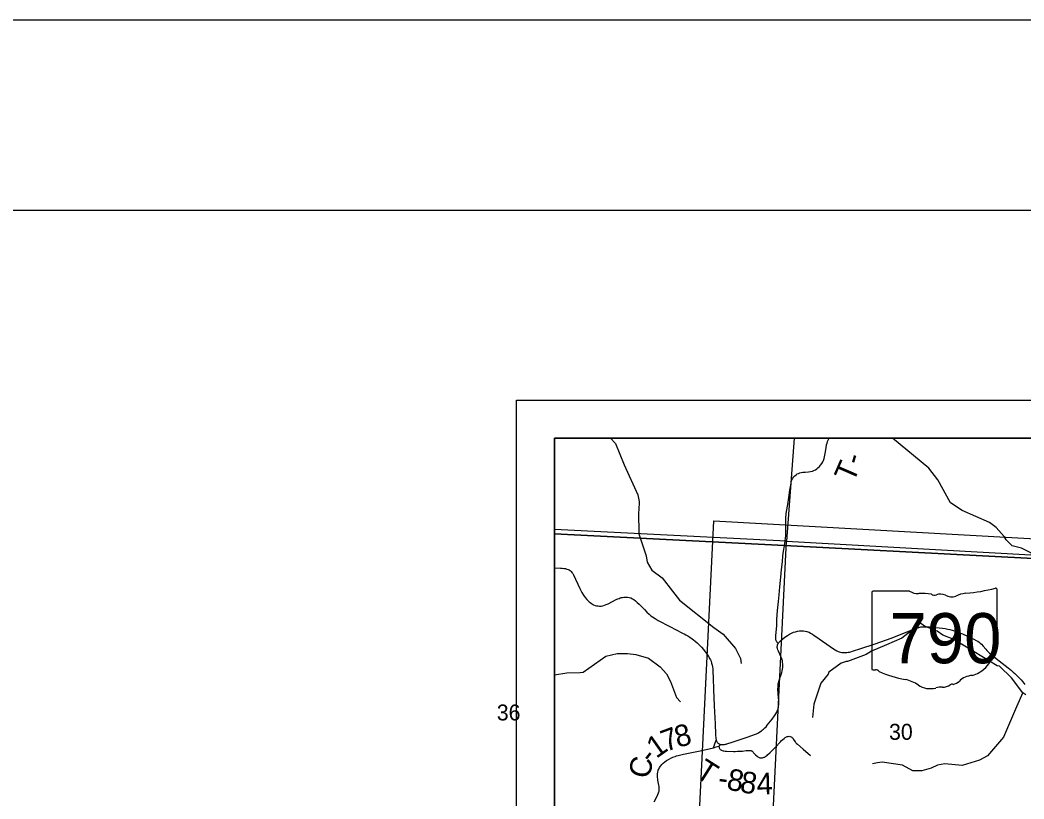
# Model space of a CAD drawing. Extents: x 0 to 34, y 0 to 22.
# Drawn here: x 22.432 to 25.071, y 19.951 to 22 of the extents above; entities that cross this region are included whole.
import ezdxf

# ---------------------------------------------------------------- set-up
doc = ezdxf.new("R2010")
doc.units = 0
for name, color, linetype in [('GM_X_County_Road', 7, 'Continuous'), ('GM_X_County_Road_Text', 7, 'Continuous'), ('GM_X_County_Text', 7, 'Continuous'), ('GM_X_Minor_River', 7, 'Continuous'), ('GM_X_Section', 7, 'Continuous'), ('GM_X_Section_Text', 7, 'Continuous'), ('GM_X_State_Location', 7, 'Continuous'), ('GM_X_State_Route', 7, 'Continuous'), ('GM_X_State_Shield', 7, 'Continuous'), ('GM_X_Township_Road', 7, 'Continuous'), ('GM_X_Township_Road_Text', 7, 'Continuous'), ('SH_Border', 7, 'Continuous'), ('SH_Cut_Line', 7, 'Continuous'), ('SH_Data', 7, 'Continuous')]:
    doc.layers.add(name, color=color, linetype=linetype)

msp = doc.modelspace()

# ---------------------------------------------------------------- linework, layer by layer
at = {"layer": 'GM_X_County_Road'}
for points in [[(24.0993, 19.9439), (24.1068, 19.9581), (24.1088, 19.9625), (24.1106, 19.9668), (24.1114, 19.9694), (24.112, 19.9719), (24.1124, 19.9747), (24.1125, 19.9775), (24.1126, 19.9805), (24.1124, 19.9839), (24.1119, 19.9873), (24.111, 19.9919), (24.1093, 20.0001), (24.1086, 20.0042), (24.1081, 20.0077), (24.1079, 20.012), (24.1082, 20.0171), (24.1089, 20.0214), (24.1101, 20.0264), (24.1112, 20.0293), (24.1135, 20.0339), (24.1164, 20.0381), (24.1192, 20.0414), (24.1228, 20.045), (24.1272, 20.0486), (24.1318, 20.0519), (24.1371, 20.0552), (24.1427, 20.0581), (24.1484, 20.0607), (24.1542, 20.0628), (24.1582, 20.0641), (24.1626, 20.0653), (24.1695, 20.0671), (24.1764, 20.0687), (24.2158, 20.0766), (24.2362, 20.0813), (24.2549, 20.0859), (24.2581, 20.0868), (24.2626, 20.0881), (24.2659, 20.089), (24.2692, 20.0902), (24.2703, 20.0907), (24.2711, 20.0912), (24.2718, 20.0918), (24.2722, 20.0925), (24.2727, 20.0936), (24.2731, 20.0946)], [(24.2549, 20.0859), (24.2569, 20.0908), (24.26, 20.0985), (24.2627, 20.1053)]]:
    msp.add_lwpolyline(points, dxfattribs=at)
at = {"layer": 'GM_X_County_Text'}
msp.add_lwpolyline([(28.6466, 20.9), (23.8372, 20.9), (23.8372, 20.6485), (24.4417, 20.6174), (26.0533, 20.5337), (26.781, 20.4973), (27.0539, 20.4845), (27.8401, 20.4449), (28.6062, 20.4055)], close=True, dxfattribs=at)
msp.add_lwpolyline([(28.4159, 17.3358), (28.4427, 17.7695), (28.4677, 18.1732), (28.5249, 19.1245), (28.5443, 19.4375), (28.5808, 20.0106), (28.6062, 20.4055), (27.8401, 20.4449), (27.0539, 20.4845), (26.781, 20.4973), (26.0533, 20.5337), (24.4417, 20.6174), (23.8372, 20.6485), (23.8372, 14.4177)], dxfattribs=at)
at = {"layer": 'GM_X_Minor_River'}
for points in [[(23.9847, 20.9), (23.9979, 20.8861), (24.0204, 20.8296), (24.0562, 20.7513), (24.0602, 20.7333), (24.0588, 20.7106), (24.0578, 20.7053), (24.0592, 20.6487), (24.0782, 20.5907), (24.0807, 20.5743), (24.0933, 20.553), (24.1199, 20.5324), (24.1472, 20.4974), (24.1658, 20.4744), (24.2562, 20.4024), (24.281, 20.3849), (24.3135, 20.3466), (24.3259, 20.3208), (24.3278, 20.3078)], [(25.2864, 20.2653), (25.2899, 20.2985), (25.2843, 20.3146), (25.2738, 20.3301), (25.267, 20.3546), (25.2547, 20.4223), (25.2197, 20.4667), (25.1882, 20.5125), (25.1779, 20.5208), (25.1347, 20.5427), (25.1201, 20.5587), (25.0914, 20.5976), (25.0653, 20.6109), (25.0406, 20.617), (25.0244, 20.6327), (25.0194, 20.6416), (24.9986, 20.6647), (24.9808, 20.6786), (24.9092, 20.7101), (24.8788, 20.7304), (24.8447, 20.7904), (24.8211, 20.8215), (24.7261, 20.9)], [(25.0766, 20.2247), (25.069, 20.23), (25.0388, 20.2698), (25.007, 20.3001), (25.0013, 20.3013), (24.9204, 20.3505), (24.8856, 20.3717), (24.8587, 20.3823), (24.8432, 20.3921), (24.8099, 20.4057), (24.7967, 20.4148), (24.7925, 20.4167), (24.7831, 20.4003), (24.7665, 20.3866), (24.7506, 20.374), (24.7098, 20.3564), (24.6705, 20.34), (24.6569, 20.3308), (24.6078, 20.3129), (24.604, 20.3125), (24.5912, 20.3079), (24.5587, 20.2842), (24.5568, 20.2797), (24.5375, 20.2557), (24.5243, 20.2165), (24.5194, 20.2001), (24.5157, 20.1655)], [(23.8372, 20.2777), (23.87, 20.2826), (23.9049, 20.2837), (23.9128, 20.285), (23.9719, 20.3264), (24.0016, 20.3338), (24.0288, 20.3337), (24.0511, 20.3311), (24.0848, 20.3216), (24.1147, 20.2987), (24.1319, 20.2799), (24.1423, 20.2602), (24.1584, 20.2179), (24.1682, 20.2066)], [(25.0682, 20.2311), (25.0516, 20.1936), (25.0174, 20.1135), (24.9755, 20.0643), (24.9551, 20.0535), (24.9089, 20.0394), (24.8633, 20.0432), (24.8443, 20.0396), (24.8275, 20.0322), (24.803, 20.0246), (24.7792, 20.0253), (24.7525, 20.0403), (24.6987, 20.0477), (24.6869, 20.0458), (24.6736, 20.0435)]]:
    msp.add_lwpolyline(points, dxfattribs=at)
at = {"layer": 'GM_X_Section'}
msp.add_lwpolyline([(24.2561, 20.6827), (25.3065, 20.6239), (25.2325, 19.5985), (24.2052, 19.6482)], close=True, dxfattribs=at)
at = {"layer": 'GM_X_State_Route'}
msp.add_lwpolyline([(23.8372, 20.5589), (23.8528, 20.5583), (23.8573, 20.558), (23.8621, 20.5575), (23.8659, 20.5569), (23.8698, 20.5559), (23.8729, 20.555), (23.8756, 20.5537), (23.8783, 20.5519), (23.8809, 20.5494), (23.8832, 20.5468), (23.8852, 20.5437), (23.8872, 20.5404), (23.904, 20.5051), (23.9093, 20.4945), (23.9137, 20.487), (23.9181, 20.4808), (23.922, 20.4759), (23.9256, 20.4719), (23.9282, 20.4695), (23.9308, 20.4674), (23.9341, 20.4649), (23.9372, 20.4631), (23.9401, 20.4617), (23.9443, 20.4601), (23.9473, 20.4593), (23.9517, 20.4587), (23.9557, 20.4584), (23.96, 20.4586), (23.9644, 20.4594), (23.9687, 20.4606), (23.9734, 20.4623), (23.9786, 20.4646), (23.999, 20.4753), (24.0015, 20.4765), (24.004, 20.4776), (24.0069, 20.4787), (24.0097, 20.4797), (24.0128, 20.4807), (24.0159, 20.4814), (24.0193, 20.4818), (24.0223, 20.482), (24.0251, 20.482), (24.0295, 20.4817), (24.0337, 20.481), (24.0376, 20.4798), (24.0422, 20.4778), (24.0461, 20.4753), (24.0506, 20.472), (24.0549, 20.4681), (24.06, 20.4632), (24.0735, 20.4491), (24.0801, 20.4426), (24.0861, 20.4371), (24.0909, 20.4332), (24.0949, 20.4302), (24.1022, 20.4254), (24.1097, 20.4209), (24.1409, 20.4044), (24.1736, 20.3876), (24.1785, 20.385), (24.1828, 20.3826), (24.1876, 20.3798), (24.1928, 20.3764), (24.1988, 20.3721), (24.2026, 20.3694), (24.207, 20.3662), (24.2125, 20.3614), (24.2183, 20.3557), (24.224, 20.3499), (24.2289, 20.3443), (24.2336, 20.3384), (24.2379, 20.3324), (24.2423, 20.3259), (24.2458, 20.3196), (24.2474, 20.3166), (24.2488, 20.3133), (24.2504, 20.3085), (24.2517, 20.3034), (24.2527, 20.2982), (24.2532, 20.2933), (24.2536, 20.2875), (24.2545, 20.269), (24.2552, 20.2387), (24.2573, 20.196), (24.2596, 20.1485), (24.2605, 20.1213), (24.2608, 20.1174), (24.2612, 20.1138), (24.2615, 20.1108), (24.2618, 20.1091), (24.2622, 20.1074), (24.2627, 20.1053), (24.2633, 20.1035), (24.2643, 20.1016), (24.2652, 20.1003), (24.2662, 20.0991), (24.2674, 20.0978), (24.2686, 20.0969), (24.2699, 20.0961), (24.2711, 20.0954), (24.2722, 20.0949), (24.2731, 20.0946), (24.2739, 20.0943), (24.2751, 20.0941), (24.2765, 20.094), (24.2779, 20.0939), (24.2793, 20.0939), (24.2809, 20.0941), (24.2826, 20.0942), (24.2845, 20.0945), (24.2864, 20.0949), (24.2884, 20.0954), (24.2902, 20.0959), (24.304, 20.1003), (24.3442, 20.1136), (24.356, 20.1177), (24.363, 20.1203), (24.3681, 20.1225), (24.3732, 20.125), (24.3775, 20.1274), (24.3811, 20.1301), (24.3842, 20.1325), (24.3871, 20.135), (24.3905, 20.138), (24.3935, 20.141), (24.3967, 20.1448), (24.4099, 20.1613), (24.4155, 20.1693), (24.4192, 20.1749), (24.4215, 20.1791), (24.4228, 20.1821), (24.4238, 20.185), (24.4249, 20.1884), (24.4258, 20.1916), (24.4263, 20.1945), (24.4266, 20.197), (24.4268, 20.1995), (24.4269, 20.2021), (24.4269, 20.2045), (24.4267, 20.2094), (24.4252, 20.2264), (24.4249, 20.2315), (24.4247, 20.2371), (24.4248, 20.2412), (24.4249, 20.2448), (24.4251, 20.2482), (24.4254, 20.251), (24.4257, 20.2538), (24.4262, 20.2569), (24.4268, 20.2596), (24.4276, 20.2624), (24.4286, 20.2658), (24.4337, 20.2812), (24.4346, 20.284), (24.4356, 20.2874), (24.4362, 20.2895), (24.4367, 20.2918), (24.437, 20.2941), (24.4373, 20.2964), (24.4375, 20.2992), (24.4373, 20.3066), (24.4371, 20.3097), (24.4369, 20.3124), (24.4364, 20.3148), (24.4358, 20.3173), (24.4352, 20.3197), (24.4343, 20.3221), (24.4335, 20.324), (24.4326, 20.3262), (24.4259, 20.3394), (24.4244, 20.343), (24.4234, 20.3464), (24.4229, 20.3495), (24.423, 20.3517), (24.4232, 20.3539), (24.4238, 20.3566), (24.4246, 20.3589), (24.4251, 20.3598), (24.4259, 20.3612), (24.4271, 20.3628), (24.4285, 20.3644), (24.4322, 20.3677), (24.4374, 20.372), (24.4431, 20.3765), (24.4495, 20.3808), (24.4549, 20.3842), (24.4601, 20.3871), (24.4656, 20.3895), (24.4707, 20.3911), (24.4765, 20.3925), (24.4816, 20.3932), (24.4866, 20.3934), (24.4915, 20.3932), (24.4961, 20.3927), (24.5009, 20.3916), (24.5037, 20.3907), (24.5064, 20.3895), (24.5107, 20.3871), (24.5157, 20.3841), (24.5199, 20.3814), (24.5247, 20.3781), (24.571, 20.3459), (24.5752, 20.3432), (24.5792, 20.341), (24.583, 20.3393), (24.5859, 20.3381), (24.5891, 20.3372), (24.5924, 20.3366), (24.5953, 20.3363), (24.5984, 20.3361), (24.6014, 20.3362), (24.6038, 20.3363), (24.6062, 20.3365), (24.6095, 20.337), (24.6126, 20.3376), (24.6164, 20.3384), (24.6205, 20.3394), (24.6427, 20.3468), (24.6777, 20.3586), (24.7099, 20.3696), (24.7223, 20.3741), (24.7379, 20.38), (24.7792, 20.3972), (24.7847, 20.3994), (24.7899, 20.4011), (24.7955, 20.4025), (24.8002, 20.4034), (24.8047, 20.4039), (24.8091, 20.4042), (24.8134, 20.4042), (24.8179, 20.4041), (24.8229, 20.4037), (24.8578, 20.4001), (24.8646, 20.3991), (24.8711, 20.398), (24.8768, 20.3966), (24.8824, 20.395), (24.8976, 20.3898), (24.9097, 20.3851), (24.9229, 20.3795), (24.9319, 20.3753), (24.9397, 20.3715), (24.9456, 20.3683), (24.9499, 20.3658), (24.9534, 20.3634), (24.9565, 20.3608), (24.9598, 20.3578), (24.9645, 20.3529), (24.9712, 20.3452), (24.9741, 20.3418), (24.9775, 20.3383), (24.9811, 20.3349), (24.9852, 20.3314), (24.9894, 20.3281), (24.994, 20.3244), (25.0147, 20.3084), (25.0302, 20.2961), (25.0341, 20.2928), (25.0388, 20.2889), (25.0435, 20.2849), (25.0476, 20.2813), (25.0513, 20.2778), (25.0548, 20.2743), (25.0583, 20.2708), (25.0613, 20.2674), (25.064, 20.2643), (25.0683, 20.259), (25.0709, 20.2557), (25.0739, 20.2523)], dxfattribs=at)
at = {"layer": 'GM_X_State_Shield'}
for p, q in [((24.6712, 20.494), (24.6712, 20.2939)), ((24.771, 20.4974), (24.6745, 20.4974)), ((25.0008, 20.3977), (25.0008, 20.5024)), ((25.0008, 20.3977), (25.0008, 20.3977))]:
    msp.add_line(p, q, dxfattribs=at)
for points in [[(25.5135, 20.9), (24.4676, 20.9), (24.4469, 20.6293), (25.4973, 20.5705)], [(23.8372, 20.6603), (23.8372, 19.6255), (24.396, 19.5948), (24.4469, 20.6293)]]:
    msp.add_lwpolyline(points, close=True, dxfattribs=at)
for centre, major_axis, start_param, end_param in [((24.675, 20.4944), (0.00382, 0), 1.712693, 3.28349), ((24.794, 20.5207), (0.037, 0), 4.042523, 4.731795), ((24.8063, 20.3851), (0.133, 0), 1.404758, 1.657858), ((24.8364, 20.4955), (0.0107, 0), 3.836095, 5.185415), ((24.8521, 20.4723), (0.0222, 0), 0.950623, 2.079405), ((24.8808, 20.5041), (0.0267, 0), 4.081561, 5.145723), ((24.928, 20.4363), (0.0703, 0), 1.699011, 2.107814), ((24.8834, 20.7703), (0.3495, 0), 4.814394, 5.042369), ((24.9972, 20.5028), (0.00367, 0), 6.141152, 7.989035), ((25, 20.39), (0.00568, 0), 1.883978, 3.671073), ((24.9638, 20.3768), (0.0341, 0), 5.934695, 6.695948), ((24.9969, 20.3973), (0.00393, 0), 5.05454, 6.418171), ((24.903, 20.3406), (0.0874, 0), 5.101752, 6.440018), ((25.014, 20.3539), (0.0248, 0), 2.387724, 3.262537), ((24.675, 20.2934), (0.00385, 0), 3.00124, 4.508301), ((24.6756, 20.3139), (0.0294, 0), 4.665946, 4.897461), ((24.6816, 20.2823), (0.0106, 0), 0.519207, 1.627899), ((24.8155, 20.4621), (0.2524, 0), 4.195997, 4.488961), ((24.9398, 20.2377), (0.0479, 0), 1.647645, 2.488434), ((24.7402, 20.204), (0.079, 0), 0.823519, 1.323587), ((24.8256, 20.2813), (0.0501, 0), 4.026481, 4.996735), ((24.8546, 20.2122), (0.0412, 0), 1.495662, 1.94098), ((24.8582, 20.2664), (0.0267, 0), 4.691044, 5.507374), ((24.8824, 20.247), (0.00752, 0), 1.147584, 2.315152), ((24.8792, 20.2745), (0.0282, 0), 4.937069, 5.64225)]:
    msp.add_ellipse(centre, major_axis=major_axis, ratio=0.8, start_param=start_param, end_param=end_param, dxfattribs=at)
at = {"layer": 'GM_X_Township_Road'}
for points in [[(24.442, 20.6168), (24.4428, 20.6218), (24.444, 20.6301), (24.4448, 20.6367), (24.4454, 20.6433), (24.4458, 20.6505), (24.4459, 20.6664), (24.4457, 20.6864), (24.4459, 20.6933), (24.4461, 20.6972), (24.4465, 20.7007), (24.4476, 20.7071), (24.4505, 20.7252), (24.4534, 20.7441), (24.4563, 20.7637), (24.4582, 20.7763), (24.4595, 20.7834), (24.4606, 20.7877), (24.462, 20.7916), (24.4638, 20.7949), (24.4661, 20.7981), (24.469, 20.8011), (24.4724, 20.8038), (24.4754, 20.8059), (24.4788, 20.8075), (24.4819, 20.8088), (24.4859, 20.8099), (24.49, 20.8106), (24.4961, 20.8111), (24.5048, 20.8118), (24.5104, 20.8125), (24.5153, 20.8137), (24.5194, 20.8152), (24.5234, 20.8172), (24.5266, 20.8192), (24.53, 20.8219), (24.5337, 20.8253), (24.537, 20.8291), (24.5399, 20.8332), (24.5424, 20.8376), (24.5441, 20.8416), (24.546, 20.8469), (24.5472, 20.851), (24.5483, 20.8555), (24.5492, 20.86), (24.5515, 20.8749), (24.5528, 20.8828), (24.554, 20.8872), (24.5554, 20.8912), (24.5572, 20.8951), (24.5595, 20.9)], [(24.4251, 20.3598), (24.423, 20.3623), (24.4223, 20.3631), (24.4215, 20.3642), (24.4206, 20.3657), (24.4202, 20.3666), (24.4199, 20.3675), (24.4196, 20.3699), (24.4194, 20.3728), (24.4194, 20.3766), (24.4196, 20.3812), (24.4201, 20.3886), (24.4209, 20.3985), (24.4214, 20.4068), (24.4222, 20.4232), (24.4238, 20.447), (24.4259, 20.4702), (24.4276, 20.4882), (24.4296, 20.5087), (24.4325, 20.5344), (24.4345, 20.555), (24.4363, 20.5749), (24.438, 20.5903), (24.4396, 20.6032), (24.442, 20.6168)], [(24.2692, 20.0902), (24.2704, 20.0858), (24.271, 20.0842), (24.2719, 20.0826), (24.273, 20.0812), (24.2743, 20.0801), (24.2759, 20.0791), (24.2779, 20.0783), (24.2803, 20.0777), (24.2827, 20.0773), (24.2859, 20.0771), (24.2898, 20.0769), (24.3076, 20.0763), (24.3125, 20.0763), (24.3185, 20.0765), (24.3255, 20.0768), (24.3317, 20.0771), (24.3411, 20.0781), (24.3444, 20.0784), (24.347, 20.0786), (24.3489, 20.0787), (24.3506, 20.0786), (24.3518, 20.0785), (24.3533, 20.0782), (24.3545, 20.0778), (24.3557, 20.0773), (24.3567, 20.0766), (24.3578, 20.0758), (24.3593, 20.0742), (24.3607, 20.0727), (24.3659, 20.0672), (24.3697, 20.0637), (24.3716, 20.0622), (24.3733, 20.0612), (24.3751, 20.0602), (24.3771, 20.0595), (24.3788, 20.0591), (24.3807, 20.0589), (24.3824, 20.0589), (24.3842, 20.0592), (24.3862, 20.0598), (24.3883, 20.0606), (24.3899, 20.0614), (24.3915, 20.0622), (24.3933, 20.0633), (24.3953, 20.0648), (24.3977, 20.0668), (24.4041, 20.073), (24.4112, 20.0805), (24.4183, 20.0876), (24.4311, 20.1013), (24.4342, 20.1047), (24.4376, 20.1078), (24.4409, 20.1104), (24.4436, 20.1123), (24.4468, 20.1141), (24.4494, 20.1151), (24.452, 20.1157), (24.4543, 20.1159), (24.4558, 20.1157), (24.4573, 20.1153), (24.4592, 20.1146), (24.4609, 20.1134), (24.4622, 20.1121), (24.4635, 20.1106), (24.4646, 20.109), (24.4657, 20.1073), (24.4699, 20.1012), (24.4714, 20.0995), (24.4729, 20.0979), (24.4759, 20.0953), (24.491, 20.082), (24.5106, 20.0656)]]:
    msp.add_lwpolyline(points, dxfattribs=at)
at = {"layer": 'SH_Border'}
msp.add_lwpolyline([(1.5, 21.5), (33.5, 21.5), (33.5, 0.5), (1.5, 0.5)], close=True, dxfattribs=at)
at = {"layer": 'SH_Cut_Line'}
msp.add_lwpolyline([(0, 0), (34, 0), (34, 22), (0, 22)], close=True, dxfattribs=at)
msp.add_lwpolyline([(30.6372, 20.9), (23.8372, 20.9), (23.8372, 14.4177)], dxfattribs=at)
at = {"layer": 'SH_Data'}
for points in [[(23.7372, 21), (30.7372, 21), (30.7372, 14), (23.7372, 14)], [(23.8372, 20.9), (30.6372, 20.9), (30.6372, 14.1), (23.8372, 14.1)]]:
    msp.add_lwpolyline(points, close=True, dxfattribs=at)

# ---------------------------------------------------------------- texts
at = {"layer": 'GM_X_County_Road_Text'}
for s, rotation, p in [('7', 20.1446, (24.1296, 20.0743)), ('8', 14.0186, (24.1606, 20.0857)), ('1', 35.1341, (24.1047, 20.0561)), ('C', 77.1489, (24.0859, 20.0018)), ('-', 51.3344, (24.0933, 20.0409))]:
    msp.add_text(s, height=0.0568, rotation=rotation, dxfattribs=at).set_placement(p)
at = {"layer": 'GM_X_Section_Text'}
for s, p in [('36', (23.6855, 20.1576)), ('30', (24.7168, 20.1067))]:
    msp.add_text(s, height=0.04186, rotation=0, dxfattribs=at).set_placement(p)
at = {"layer": 'GM_X_State_Location'}
for s in ['s', 'r']:
    msp.add_text(s, height=0.000189, dxfattribs=at).set_placement((24.8323, 20.3806))
msp.add_text('790', height=0.000189, rotation=0, dxfattribs=at).set_placement((24.7655, 20.3669))
at = {"layer": 'GM_X_State_Shield'}
msp.add_text('790', height=0.13184, dxfattribs=at).set_placement((24.7182, 20.308))
at = {"layer": 'GM_X_Township_Road_Text'}
for s, rotation, p in [('-', 73.8409, (24.6425, 20.8273)), ('T', 66.7015, (24.6231, 20.781)), ('T', 327.5165, (24.2041, 20.0114)), ('8', 349.2371, (24.2874, 19.9765)), ('8', 349.7108, (24.3223, 19.9699)), ('4', 1.3983, (24.3693, 19.9627)), ('-', 352.4158, (24.2651, 19.9795))]:
    msp.add_text(s, height=0.0568, rotation=rotation, dxfattribs=at).set_placement(p)

doc.saveas('drawing.dxf')
